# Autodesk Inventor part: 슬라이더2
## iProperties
Company: 한국ATC센터
Created: 2015-04
Part Number: 슬라이더2
Document SubType Name: Modeling
Designer: KYOUNG IL JANG
Density: 1 g/cm^3
Material: 기본값
Mass: 8.7906 g
Surface Area: 52.3143 cm^2
Volume: 8.7906 cm^3
Author: KYOUNG IL JANG
